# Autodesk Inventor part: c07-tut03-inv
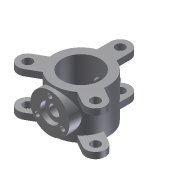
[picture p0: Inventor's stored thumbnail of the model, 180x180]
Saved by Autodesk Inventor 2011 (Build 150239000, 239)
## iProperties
Created: 2010-03
Part Number: c07-tut03-inv
Document SubType Name: Modeling
Designer: CADSoft
Density: 1 g/cm^3
Author: CADSoft
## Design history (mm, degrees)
sketch "Sketch1"
  geometry: C1 r 97 at (0, 0); C2 r 140 at (0, 0); 1 further point
  constraints: 2 centre point, 2 coincident
  dimensions: "d0" = 194 diameter of C1; "d1" = 280 diameter of C2
extrude "Extrusion1" new body sketch "Sketch1" stored distance "d2" = 225; taper "d3" = 0 deg
workplane "Work Plane1"
sketch "Sketch2"
  geometry: C1 r 100 at (0, 0); 1 further point
  constraints: 1 centre point, 1 coincident
  dimensions: "d5" = 200 diameter of C1
extrude "Extrusion2" join sketch "Sketch2" stored distance "d6" = 225; taper "d7" = 0 deg
workplane "Work Plane2"
sketch "Sketch3"
  geometry: C1 r 37.5 at (0, 0); 1 further point
  constraints: 1 centre point, 1 coincident
  dimensions: "d9" = 75 diameter of C1
extrude "Extrusion3" join sketch "Sketch3" stored distance "d10" = 225; taper "d11" = 0 deg
hole "Hole1" diameter "d14" = 56; stored, may be unused: countersink angle "d18" = 90 deg, drill point angle "d20" = 0 deg; dims "d12" = 10, "d13" = 10, "d15" = 6, "d16" = 100, "d17" = 25, "d19" = 310
sketch "Sketch4"
  geometry: C1 r 50 at (0, 0) reference; 1 further point
  constraints: 1 vertical alignment
  dimensions: "d21" = 75 distance of C1.centre point (0, 75)
hole "Hole2" sketch "Sketch4" at (0, 75) diameter "d22" = 24; stored, may be unused: countersink angle "d26" = 90 deg, drill point angle "d28" = 118 deg; dims "d23" = 6, "d24" = 100, "d25" = 25, "d27" = 15
pattern_circular "Circular Pattern1" dims angle "d30" = 360 deg
sketch "Sketch5"
  geometry: L1 (-50, 200)-(-50, 130.767); L2 (50, 200)-(50, 130.767); L3 (0, 0)-(0, 306.095); C1 r 97 at (0, 0) reference; C2 r 23.5 at (0, 200); A1 r 140 centre (0, 0) between (-50, 130.767) and (50, 130.767) reference; A2 r 50 centre (0, 200) between (50, 200) and (-50, 200); A3 r 140 centre (0, 0) between (50, 130.767) and (-50, 130.767)
  constraints: 7 point on circle, 6 end point, 3 centre point, 2 coincident, 2 tangent, 1 other
  dimensions: "d32" = 200 distance of A2.centre C1.centre; "d33" = 50 radius of A2; "d34" = 47 diameter of C2
extrude "Extrusion4" join sketch "Sketch5" distance "d35" = 32; taper "d36" = 0 deg
pattern_circular "Circular Pattern2" dims angle "d38" = 360 deg
mirror "Mirror1"
body "Solid1"
other parameters: "d8" = 325
